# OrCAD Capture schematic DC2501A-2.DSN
size Custom; title: 40VIN, 2.5A STEP DOWN µMODULE DC/DC CONVERTER; rev: 2; note: DC2501A
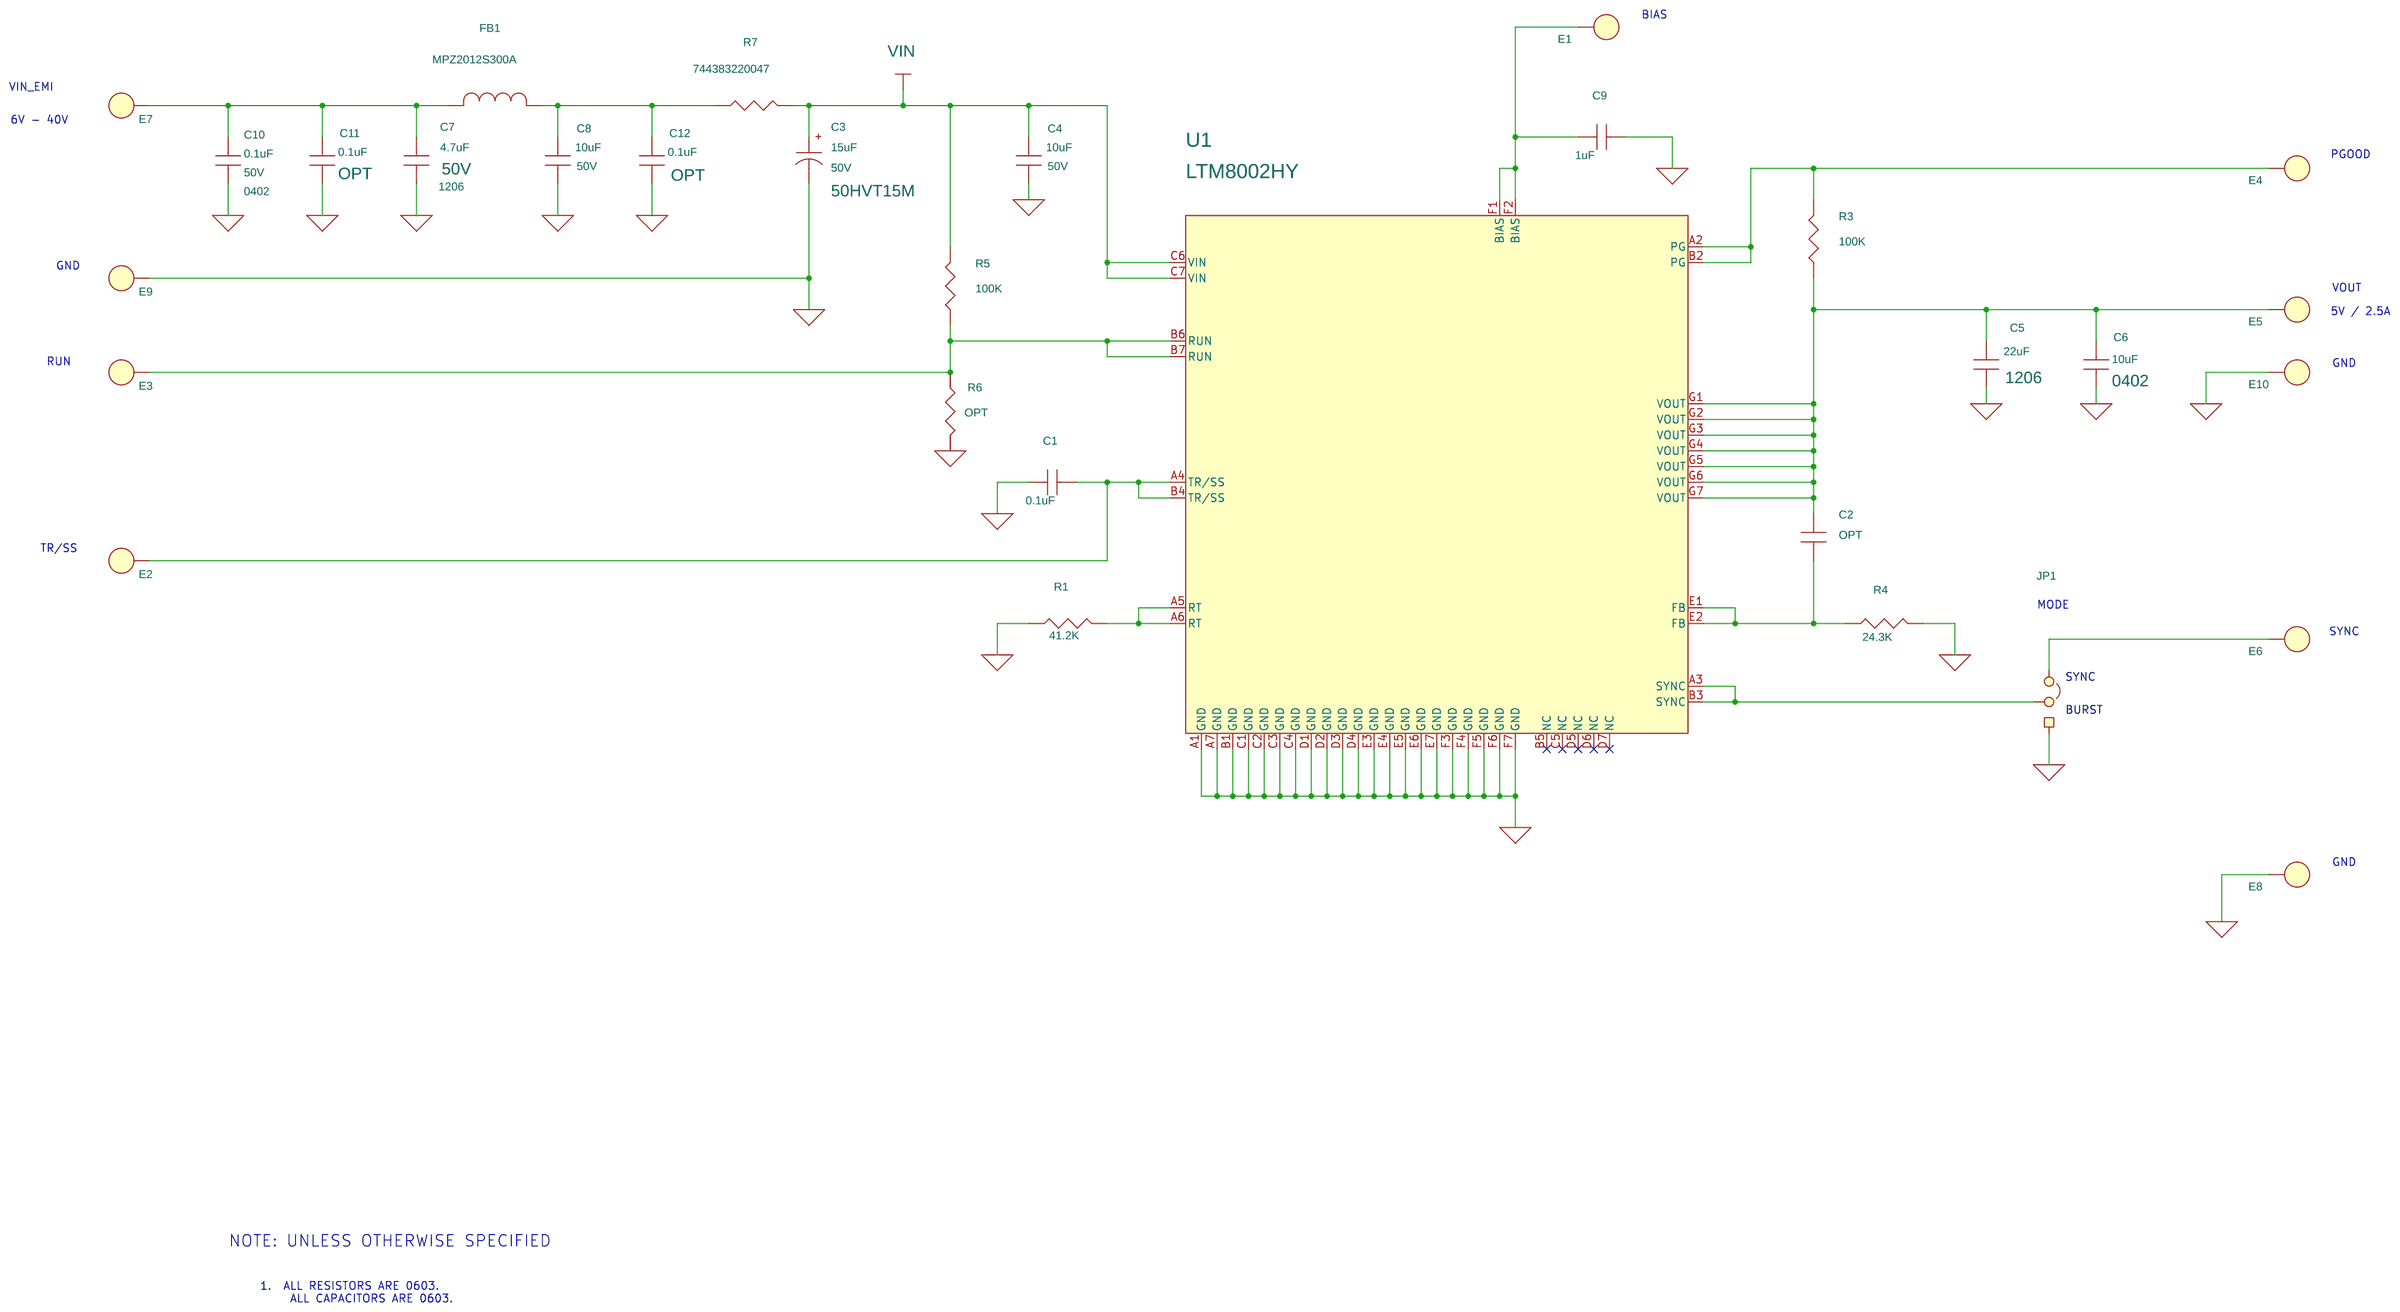
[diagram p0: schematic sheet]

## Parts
C1  0.1uF  [0603]
C2  OPT  [0603]
C3  15uF  [CAP-CV-6.3X6]
C4  10uF  [1210]
C5  22uF  [1206]
C6  10uF  [0402]
C7  4.7uF  [1206]
C8  10uF  [1210]
C9  1uF  [0603]
C10  0.1uF  [0402]
C11  0.1uF  [0603]
C12  0.1uF  [0603]
E1  Testpoint  [MM/2501]
E2  Testpoint  [MM/2501]
E3  Testpoint  [MM/2501]
E4  Testpoint  [MM/2501]
E5  Testpoint  [MM/2501]
E6  Testpoint  [MM/2501]
E7  Testpoint  [MM/2501]
E8  Testpoint  [MM/2501]
E9  Testpoint  [MM/2501]
E10  Testpoint  [MM/2501]
FB1  MPZ2012S300A  [0805]
JP1  JP3X1/079\NO\23  [JP3X1/079]
R1  41.2K  [0603]
R3  100K  [0603]
R4  24.3K  [0603]
R5  100K  [0603]
R6  OPT  [0603]
R7  744383220047  [IND-744383220047]
U1  LTM8002HY  [BGA-49L-0R8]

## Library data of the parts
C1 C2 C9 = CAP0402
C3 = CAP-CV-6.3X6: 1ST PART FIELD: 50V; 2ND PART FIELD: 20%; 3RD PART FIELD: OPT; 4TH PART FIELD: 50HVT15M
C4 C8 = CAP1210: 1ST PART FIELD: 50V
C5 = CAP1210: 1ST PART FIELD: 6.3V
C6 = CAP0603
C7 = CAP1210: 1ST PART FIELD: 50V; 2nd Part Field: OPT; SIZE: C3225X7S2A475K
C10 = CAP1210: 1ST PART FIELD: 50V; 5th Part Field: 0603; SIZE: GRM188R72A104K
C11 C12 = CAP0603: 2nd Part Field: OPT
E1-E10 = MillMax-2501_0
FB1 = IND-0603_0: 3RD PART FIELD: OPT; 4TH PART FIELD: TDK
JP1 = JP3X1_079_NO_23
R1 R3 R4 R7 = AAC-0402
R5 R6 = AAC-0603
U1 = LTM8053EV_12

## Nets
GND: C1.1 C3.2 C4.2 C5.2 C6.2 C7.2 C8.2 C9.2 C10.2 C11.2 C12.2 E8.1 E9.1 E10.1 JP1.1 R1.1 R4.2 R6.2 U1.A1(GND) U1.A7(GND) U1.B1(GND) U1.C1(GND) U1.C2(GND) U1.C3(GND) U1.C4(GND) U1.D1(GND) U1.D2(GND) U1.D3(GND) U1.D4(GND) U1.E3(GND) U1.E4(GND) U1.E5(GND) U1.E6(GND) U1.E7(GND) U1.F3(GND) U1.F4(GND) U1.F5(GND) U1.F6(GND) U1.F7(GND)
VIN: C3.1 C4.1 R5.2 R7.2 U1.C6(VIN) U1.C7(VIN)
N03966: C1.2 E2.1 U1.A4(TR/SS) U1.B4(TR/SS)
N05179: R1.2 U1.A5(RT) U1.A6(RT)
N08852: C2.1 C5.1 C6.1 E5.1 R3.1 U1.G1(VOUT) U1.G2(VOUT) U1.G3(VOUT) U1.G4(VOUT) U1.G5(VOUT) U1.G6(VOUT) U1.G7(VOUT)
N10381: C2.2 R4.1 U1.E1(FB) U1.E2(FB)
N15352: E6.1 JP1.3
N860189: E4.1 R3.2 U1.A2(PG) U1.B2(PG)
N873152: C9.1 E1.1 U1.F1(BIAS) U1.F2(BIAS)
N902712: JP1.2 U1.A3(SYNC) U1.B3(SYNC)
N942704: E3.1 R5.1 R6.1 U1.B6(RUN) U1.B7(RUN)
N973015: C8.1 C12.1 FB1.2 R7.1
N973137: C7.1 C10.1 C11.1 E7.1 FB1.1

Not connected (* = marked no-connect by the designer): U1 B5(NC)* C5(NC)* D5(NC)* D6(NC)* D7(NC)*

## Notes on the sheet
- BIAS
- VIN_EMI
- 6V - 40V
- PGOOD
- GND
- VOUT
- 5V / 2.5A
- RUN
- GND
- TR/SS
- MODE
- SYNC
- SYNC
- BURST
- GND
- NOTE: UNLESS OTHERWISE SPECIFIED
- 1.  ALL RESISTORS ARE 0603.
       ALL CAPACITORS ARE 0603.
